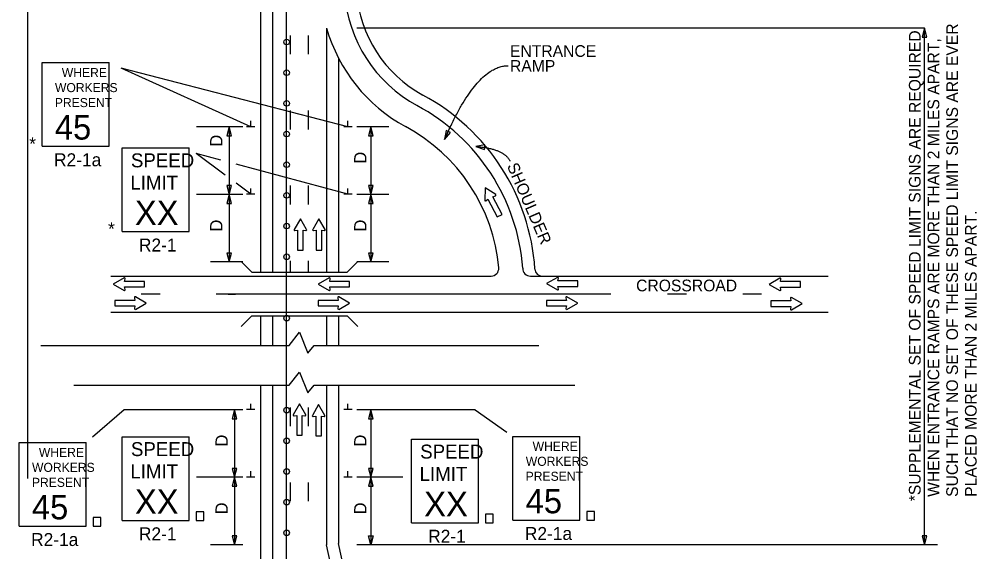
# Model space of a CAD drawing. Extents: x 16115 to 18454, y 4946 to 8326.
# Drawn here: x 16727 to 17413, y 7596 to 7978 of the extents above; entities that cross this region are included whole.
import ezdxf

# ---------------------------------------------------------------- set-up
doc = ezdxf.new("R2010")
doc.units = 0
for name, color, linetype in [('BORDER', 7, 'Continuous'), ('Level 10', 7, 'Continuous'), ('MT_SCRATCH_LEVEL_E', 7, 'Continuous'), ('PAVT_EDGE_EX', 7, 'Continuous'), ('SCRATCH_LEVEL_A', 7, 'Continuous'), ('TYPICAL_TEXT_DIMEN_EX', 7, 'Continuous')]:
    doc.layers.add(name, color=color, linetype=linetype)

# ---------------------------------------------------------------- blocks, each defined once
blk = doc.blocks.new('FTERM')
at = {"layer": 'BORDER'}
for p, q in [((-5.862, 0), (-5.862, 1.571)), ((-5.862, 1.571), (0, 0)), ((0, 0), (-5.862, -1.571)), ((-5.862, -1.571), (-5.862, 0))]:
    blk.add_line(p, q, dxfattribs=at)

msp = doc.modelspace()

# ---------------------------------------------------------------- linework, layer by layer
at = {"layer": 'BORDER'}
for p, q in [((17375.66, 7971.33), (16968.59, 7971.33)), ((17375.66, 7971.33), (17373.96, 7964.93)), ((17375.66, 7600.76), (17375.66, 7971.33)), ((17377.35, 7964.93), (17375.66, 7971.33)), ((17373.96, 7964.93), (17375.66, 7964.93)), ((17375.66, 7964.93), (17377.35, 7964.93)), ((16962.35, 7900.56), (16799.79, 7942.58)), ((16892.63, 7900.56), (16799.79, 7942.58)), ((16892.63, 7900.56), (16892.63, 7904.75)), ((16962.35, 7900.56), (16962.35, 7904.75)), ((16886.89, 7900.47), (16853.73, 7900.47)), ((16877.08, 7900.47), (16875.39, 7894.06)), ((16877.08, 7900.47), (16877.08, 7852.03)), ((16878.78, 7894.06), (16877.08, 7900.47)), ((16895.66, 7900.56), (16889.61, 7900.56)), ((16965.37, 7900.56), (16959.32, 7900.56)), ((16991.66, 7900.47), (16968.59, 7900.47)), ((16978.69, 7900.47), (16977, 7894.06)), ((16978.69, 7900.47), (16978.69, 7852.03)), ((16980.39, 7894.06), (16978.69, 7900.47)), ((17032.65, 7897.88), (17031.59, 7891.34)), ((17034.2, 7897.18), (17032.65, 7897.88)), ((17035.74, 7896.49), (17034.2, 7897.18)), ((16875.39, 7894.06), (16877.08, 7894.06)), ((16877.08, 7894.06), (16878.78, 7894.06)), ((16977, 7894.06), (16978.69, 7894.06)), ((16978.69, 7894.06), (16980.39, 7894.06)), ((17031.59, 7891.34), (17035.74, 7896.49)), ((17060.53, 7887.65), (17054.02, 7886.43)), ((17054.02, 7886.43), (17060.28, 7884.27)), ((17060.28, 7884.27), (17060.41, 7885.96)), ((17060.41, 7885.96), (17060.53, 7887.65)), ((16874.33, 7865.82), (16853.48, 7881.41)), ((16871.29, 7876.62), (16853.48, 7881.41)), ((16962.35, 7852.13), (16882.2, 7873.69)), ((16877.08, 7858.44), (16875.39, 7858.44)), ((16875.39, 7858.44), (16877.08, 7852.03)), ((16877.08, 7852.03), (16878.78, 7858.44)), ((16878.78, 7858.44), (16877.08, 7858.44)), ((16892.63, 7852.13), (16882.06, 7860.04)), ((16892.63, 7852.13), (16892.63, 7856.32)), ((16962.35, 7852.13), (16962.35, 7856.32)), ((16978.69, 7858.44), (16977, 7858.44)), ((16977, 7858.44), (16978.69, 7852.03)), ((16978.69, 7852.03), (16980.39, 7858.44)), ((16980.39, 7858.44), (16978.69, 7858.44)), ((16886.89, 7852.03), (16853.73, 7852.03)), ((16877.08, 7852.03), (16875.39, 7845.63)), ((16877.08, 7852.03), (16877.08, 7803.6)), ((16878.78, 7845.63), (16877.08, 7852.03)), ((16895.66, 7852.13), (16889.61, 7852.13)), ((16965.37, 7852.13), (16959.32, 7852.13)), ((16991.66, 7852.03), (16968.59, 7852.03)), ((16978.69, 7852.03), (16977, 7845.63)), ((16978.69, 7852.03), (16978.69, 7803.6)), ((16980.39, 7845.63), (16978.69, 7852.03)), ((16875.39, 7845.63), (16877.08, 7845.63)), ((16877.08, 7845.63), (16878.78, 7845.63)), ((16977, 7845.63), (16978.69, 7845.63)), ((16978.69, 7845.63), (16980.39, 7845.63)), ((16877.08, 7810.01), (16875.39, 7810.01)), ((16875.39, 7810.01), (16877.08, 7803.6)), ((16877.08, 7803.6), (16878.78, 7810.01)), ((16878.78, 7810.01), (16877.08, 7810.01)), ((16978.69, 7810.01), (16977, 7810.01)), ((16977, 7810.01), (16978.69, 7803.6)), ((16978.69, 7803.6), (16980.39, 7810.01)), ((16980.39, 7810.01), (16978.69, 7810.01)), ((16886.89, 7803.6), (16863.83, 7803.6)), ((16991.66, 7803.6), (16968.59, 7803.6)), ((16742.11, 7743.77), (16920.18, 7743.77)), ((16938.04, 7743.77), (17099.27, 7743.77)), ((16765.79, 7715.22), (16920.18, 7715.22)), ((16938.04, 7715.22), (17124.97, 7715.22)), ((16801.89, 7697.62), (16779.08, 7678.07)), ((16886.89, 7697.62), (16801.89, 7697.62)), ((16880.94, 7697.62), (16879.24, 7691.22)), ((16880.94, 7697.62), (16880.94, 7649.19)), ((16882.63, 7691.22), (16880.94, 7697.62)), ((16895.66, 7697.72), (16889.61, 7697.72)), ((16892.63, 7697.72), (16892.63, 7701.91)), ((16965.37, 7697.72), (16959.32, 7697.72)), ((16962.35, 7697.72), (16962.35, 7701.91)), ((17053.59, 7697.62), (16968.59, 7697.62)), ((16978.69, 7697.62), (16977, 7691.22)), ((16978.69, 7697.62), (16978.69, 7649.19)), ((16980.39, 7691.22), (16978.69, 7697.62)), ((17053.59, 7697.62), (17076.23, 7681.62)), ((16879.24, 7691.22), (16880.94, 7691.22)), ((16880.94, 7691.22), (16882.63, 7691.22)), ((16977, 7691.22), (16978.69, 7691.22)), ((16978.69, 7691.22), (16980.39, 7691.22)), ((16880.94, 7655.6), (16879.24, 7655.6)), ((16879.24, 7655.6), (16880.94, 7649.19)), ((16880.94, 7649.19), (16882.63, 7655.6)), ((16882.63, 7655.6), (16880.94, 7655.6)), ((16892.63, 7649.29), (16892.63, 7653.48)), ((16962.35, 7649.29), (16962.35, 7653.48)), ((16978.69, 7655.6), (16977, 7655.6)), ((16977, 7655.6), (16978.69, 7649.19)), ((16978.69, 7649.19), (16980.39, 7655.6)), ((16980.39, 7655.6), (16978.69, 7655.6)), ((16886.89, 7649.19), (16853.73, 7649.19)), ((16880.94, 7649.19), (16879.24, 7642.79)), ((16879.24, 7642.79), (16880.94, 7642.79)), ((16880.94, 7649.19), (16880.94, 7600.76)), ((16882.63, 7642.79), (16880.94, 7649.19)), ((16880.94, 7642.79), (16882.63, 7642.79)), ((16895.66, 7649.29), (16889.61, 7649.29)), ((16965.37, 7649.29), (16959.32, 7649.29)), ((17001.75, 7649.19), (16968.59, 7649.19)), ((16978.69, 7649.19), (16977, 7642.79)), ((16977, 7642.79), (16978.69, 7642.79)), ((16978.69, 7649.19), (16978.69, 7600.76)), ((16980.39, 7642.79), (16978.69, 7649.19)), ((16978.69, 7642.79), (16980.39, 7642.79)), ((16880.94, 7607.17), (16879.24, 7607.17)), ((16879.24, 7607.17), (16880.94, 7600.76)), ((16880.94, 7600.76), (16882.63, 7607.17)), ((16882.63, 7607.17), (16880.94, 7607.17)), ((17375.66, 7607.17), (17373.96, 7607.17)), ((17373.96, 7607.17), (17375.66, 7600.76)), ((17375.66, 7600.76), (17377.35, 7607.17)), ((17377.35, 7607.17), (17375.66, 7607.17)), ((16886.89, 7600.76), (16863.83, 7600.76)), ((17384.95, 7600.76), (16968.59, 7600.76))]:
    msp.add_line(p, q, dxfattribs=at)
msp.add_lwpolyline([(16918.32, 7255.33), (16918.32, 8189.12)], dxfattribs=at)
for centre in [(16918.32, 7961.33), (16918.32, 7939.33), (16918.32, 7917.33), (16918.32, 7895.33), (16918.32, 7873.33), (16918.32, 7851.33), (16918.32, 7829.33), (16918.32, 7807.33), (16918.32, 7763.33), (16918.32, 7697.33), (16918.32, 7675.33), (16918.32, 7653.33), (16918.32, 7631.33), (16918.32, 7609.33)]:
    msp.add_circle(centre, 2, dxfattribs=at)
for points in [[(17031.62, 7891.38), (17054.35, 7944.33), (17077.07, 7944.33)], [(17054.02, 7886.43), (17074.27, 7884.94), (17078.5, 7875.93)]]:
    msp.add_open_spline(points, degree=2, dxfattribs=at)
at = {"layer": 'Level 10'}
for p, q in [((16743.01, 7946.55), (16791.01, 7946.55)), ((16743.01, 7886.55), (16743.01, 7946.55)), ((16791.01, 7886.55), (16791.01, 7946.55)), ((16743.01, 7886.55), (16791.01, 7886.55)), ((16800.44, 7885.4), (16848.44, 7885.4)), ((16800.44, 7825.4), (16800.44, 7885.4)), ((16848.44, 7825.4), (16848.44, 7885.4)), ((16800.44, 7825.4), (16848.44, 7825.4)), ((16800.44, 7678.3), (16848.44, 7678.3)), ((16800.44, 7618.3), (16800.44, 7678.3)), ((16848.44, 7618.3), (16848.44, 7678.3)), ((17080.59, 7678.54), (17128.59, 7678.54)), ((17080.59, 7618.54), (17080.59, 7678.54)), ((17128.59, 7618.54), (17128.59, 7678.54)), ((16726.57, 7674.21), (16774.57, 7674.21)), ((16726.57, 7614.21), (16726.57, 7674.21)), ((16774.57, 7614.21), (16774.57, 7674.21)), ((17007.83, 7676.54), (17055.83, 7676.54)), ((17007.83, 7616.54), (17007.83, 7676.54)), ((17055.83, 7616.54), (17055.83, 7676.54)), ((16800.44, 7618.3), (16848.44, 7618.3)), ((17007.83, 7616.54), (17055.83, 7616.54)), ((17080.59, 7618.54), (17128.59, 7618.54)), ((16726.57, 7614.21), (16774.57, 7614.21))]:
    msp.add_line(p, q, dxfattribs=at)
for points in [[(16853.46, 7618.3), (16859.05, 7618.3), (16859.05, 7624.47), (16853.46, 7624.47)], [(17060.85, 7616.54), (17066.44, 7616.54), (17066.44, 7622.71), (17060.85, 7622.71)], [(17133.6, 7618.54), (17139.2, 7618.54), (17139.2, 7624.71), (17133.6, 7624.71)], [(16779.59, 7614.21), (16785.18, 7614.21), (16785.18, 7620.38), (16779.59, 7620.38)]]:
    msp.add_lwpolyline(points, close=True, dxfattribs=at)
at = {"layer": 'MT_SCRATCH_LEVEL_E'}
for p, q in [((17060.69, 7856.76), (17060.35, 7847.8)), ((17068.24, 7851.9), (17060.69, 7856.76)), ((17061.15, 7847.39), (17062.69, 7848.57)), ((17062.69, 7848.57), (17069.27, 7835.91)), ((17066.27, 7850.43), (17068.12, 7851.01)), ((17072.84, 7837.76), (17066.27, 7850.43)), ((17069.27, 7835.91), (17072.84, 7837.76)), ((16928.22, 7834.63), (16923.79, 7826.84)), ((16932.68, 7826.84), (16928.22, 7834.63)), ((16941.46, 7834.63), (16937.03, 7826.84)), ((16945.92, 7826.84), (16941.46, 7834.63)), ((16924.31, 7826.1), (16926.22, 7826.44)), ((16926.22, 7826.44), (16926.22, 7812.17)), ((16930.25, 7812.17), (16930.25, 7826.44)), ((16930.25, 7826.44), (16932.16, 7826.1)), ((16937.55, 7826.1), (16939.46, 7826.44)), ((16939.46, 7826.44), (16939.46, 7812.17)), ((16943.49, 7812.17), (16943.49, 7826.44)), ((16943.49, 7826.44), (16945.4, 7826.1)), ((16926.22, 7812.17), (16930.25, 7812.17)), ((16939.46, 7812.17), (16943.49, 7812.17)), ((16801.82, 7792.13), (16794.02, 7787.67)), ((16801.82, 7792.13), (16794.02, 7787.67)), ((16794.02, 7787.67), (16801.82, 7783.24)), ((16794.02, 7787.67), (16801.82, 7783.24)), ((16802.21, 7789.7), (16802.55, 7791.62)), ((16802.21, 7789.7), (16802.55, 7791.62)), ((16816.48, 7789.7), (16802.21, 7789.7)), ((16816.48, 7789.7), (16802.21, 7789.7)), ((16816.48, 7785.68), (16816.48, 7789.7)), ((16816.48, 7785.68), (16816.48, 7789.7)), ((16948.83, 7792.13), (16941.04, 7787.67)), ((16948.83, 7792.13), (16941.04, 7787.67)), ((16941.04, 7787.67), (16948.83, 7783.24)), ((16941.04, 7787.67), (16948.83, 7783.24)), ((16949.23, 7789.7), (16949.57, 7791.62)), ((16949.23, 7789.7), (16949.57, 7791.62)), ((16963.5, 7789.7), (16949.23, 7789.7)), ((16963.5, 7789.7), (16949.23, 7789.7)), ((16963.5, 7785.68), (16963.5, 7789.7)), ((16963.5, 7785.68), (16963.5, 7789.7)), ((17112.45, 7792.54), (17104.66, 7788.07)), ((17112.45, 7792.54), (17104.66, 7788.07)), ((17104.66, 7788.07), (17112.45, 7783.65)), ((17104.66, 7788.07), (17112.45, 7783.65)), ((17112.85, 7790.11), (17113.19, 7792.02)), ((17112.85, 7790.11), (17113.19, 7792.02)), ((17127.12, 7790.11), (17112.85, 7790.11)), ((17127.12, 7790.11), (17112.85, 7790.11)), ((17127.12, 7786.08), (17127.12, 7790.11)), ((17127.12, 7786.08), (17127.12, 7790.11)), ((17272.01, 7791.93), (17264.22, 7787.47)), ((17272.01, 7791.93), (17264.22, 7787.47)), ((17264.22, 7787.47), (17272.01, 7783.05)), ((17264.22, 7787.47), (17272.01, 7783.05)), ((17272.41, 7789.51), (17272.74, 7791.42)), ((17272.41, 7789.51), (17272.74, 7791.42)), ((17286.67, 7789.51), (17272.41, 7789.51)), ((17286.67, 7789.51), (17272.41, 7789.51)), ((17286.67, 7785.48), (17286.67, 7789.51)), ((17286.67, 7785.48), (17286.67, 7789.51)), ((16802.55, 7783.76), (16802.21, 7785.68)), ((16802.21, 7785.68), (16816.48, 7785.68)), ((16802.55, 7783.76), (16802.21, 7785.68)), ((16802.21, 7785.68), (16816.48, 7785.68)), ((16949.57, 7783.76), (16949.23, 7785.68)), ((16949.23, 7785.68), (16963.5, 7785.68)), ((16949.57, 7783.76), (16949.23, 7785.68)), ((16949.23, 7785.68), (16963.5, 7785.68)), ((17113.19, 7784.17), (17112.85, 7786.08)), ((17112.85, 7786.08), (17127.12, 7786.08)), ((17113.19, 7784.17), (17112.85, 7786.08)), ((17112.85, 7786.08), (17127.12, 7786.08)), ((17272.74, 7783.57), (17272.41, 7785.48)), ((17272.41, 7785.48), (17286.67, 7785.48)), ((17272.74, 7783.57), (17272.41, 7785.48)), ((17272.41, 7785.48), (17286.67, 7785.48)), ((16809.52, 7776.08), (16795.25, 7776.08)), ((16795.25, 7776.08), (16795.25, 7772.06)), ((16809.52, 7776.08), (16795.25, 7776.08)), ((16795.25, 7776.08), (16795.25, 7772.06)), ((16809.18, 7778), (16809.52, 7776.08)), ((16809.18, 7778), (16809.52, 7776.08)), ((16817.71, 7774.09), (16809.92, 7778.51)), ((16817.71, 7774.09), (16809.92, 7778.51)), ((16809.92, 7769.63), (16817.71, 7774.09)), ((16809.92, 7769.63), (16817.71, 7774.09)), ((16955.32, 7776.08), (16941.05, 7776.08)), ((16941.05, 7776.08), (16941.05, 7772.06)), ((16955.32, 7776.08), (16941.05, 7776.08)), ((16941.05, 7776.08), (16941.05, 7772.06)), ((16954.98, 7778), (16955.32, 7776.08)), ((16954.98, 7778), (16955.32, 7776.08)), ((16963.51, 7774.09), (16955.72, 7778.51)), ((16963.51, 7774.09), (16955.72, 7778.51)), ((16955.72, 7769.63), (16963.51, 7774.09)), ((16955.72, 7769.63), (16963.51, 7774.09)), ((17118.94, 7776.08), (17104.67, 7776.08)), ((17104.67, 7776.08), (17104.67, 7772.06)), ((17118.94, 7776.08), (17104.67, 7776.08)), ((17104.67, 7776.08), (17104.67, 7772.06)), ((17118.6, 7778), (17118.94, 7776.08)), ((17118.6, 7778), (17118.94, 7776.08)), ((17127.13, 7774.09), (17119.34, 7778.51)), ((17127.13, 7774.09), (17119.34, 7778.51)), ((17119.34, 7769.63), (17127.13, 7774.09)), ((17119.34, 7769.63), (17127.13, 7774.09)), ((17279.9, 7775.78), (17265.63, 7775.78)), ((17265.63, 7775.78), (17265.63, 7771.75)), ((17279.9, 7775.78), (17265.63, 7775.78)), ((17265.63, 7775.78), (17265.63, 7771.75)), ((17279.56, 7777.69), (17279.9, 7775.78)), ((17279.56, 7777.69), (17279.9, 7775.78)), ((17288.09, 7773.78), (17280.3, 7778.21)), ((17288.09, 7773.78), (17280.3, 7778.21)), ((17280.3, 7769.32), (17288.09, 7773.78)), ((17280.3, 7769.32), (17288.09, 7773.78)), ((16795.25, 7772.06), (16809.52, 7772.06)), ((16795.25, 7772.06), (16809.52, 7772.06)), ((16809.52, 7772.06), (16809.18, 7770.14)), ((16809.52, 7772.06), (16809.18, 7770.14)), ((16941.05, 7772.06), (16955.32, 7772.06)), ((16941.05, 7772.06), (16955.32, 7772.06)), ((16955.32, 7772.06), (16954.98, 7770.14)), ((16955.32, 7772.06), (16954.98, 7770.14)), ((17104.67, 7772.06), (17118.94, 7772.06)), ((17104.67, 7772.06), (17118.94, 7772.06)), ((17118.94, 7772.06), (17118.6, 7770.14)), ((17118.94, 7772.06), (17118.6, 7770.14)), ((17265.63, 7771.75), (17279.9, 7771.75)), ((17265.63, 7771.75), (17279.9, 7771.75)), ((17279.9, 7771.75), (17279.56, 7769.84)), ((17279.9, 7771.75), (17279.56, 7769.84)), ((16927.57, 7701.78), (16923.14, 7693.99)), ((16932.03, 7693.99), (16927.57, 7701.78)), ((16941.22, 7701.32), (16936.79, 7693.53)), ((16945.68, 7693.53), (16941.22, 7701.32)), ((16923.66, 7693.25), (16925.58, 7693.59)), ((16925.58, 7693.59), (16925.58, 7679.32)), ((16929.6, 7679.32), (16929.6, 7693.59)), ((16929.6, 7693.59), (16931.52, 7693.25)), ((16937.31, 7692.79), (16939.22, 7693.13)), ((16939.22, 7693.13), (16939.22, 7678.86)), ((16943.25, 7678.86), (16943.25, 7693.13)), ((16943.25, 7693.13), (16945.16, 7692.79)), ((16925.58, 7679.32), (16929.6, 7679.32)), ((16939.22, 7678.86), (16943.25, 7678.86))]:
    msp.add_line(p, q, dxfattribs=at)
for centre, start, end in [((17067.96, 7851.48), 287.48456, 57.22148), ((17060.85, 7847.79), 177.8732, 307.41217), ((16924.23, 7826.6), 150.42484, 279.96381), ((16932.24, 7826.6), 260.03619, 29.77312), ((16937.47, 7826.6), 150.42484, 279.96381), ((16945.48, 7826.6), 260.03619, 29.77312), ((16802.06, 7791.69), 350.03619, 119.77312), ((16802.06, 7791.69), 350.03619, 119.77312), ((16949.07, 7791.69), 350.03619, 119.77312), ((16949.07, 7791.69), 350.03619, 119.77312), ((17112.69, 7792.1), 350.03619, 119.77312), ((17112.69, 7792.1), 350.03619, 119.77312), ((17272.25, 7791.49), 350.03619, 119.77312), ((17272.25, 7791.49), 350.03619, 119.77312), ((16802.06, 7783.68), 240.42484, 9.96381), ((16802.06, 7783.68), 240.42484, 9.96381), ((16949.08, 7783.68), 240.42484, 9.96381), ((16949.08, 7783.68), 240.42484, 9.96381), ((17112.7, 7784.09), 240.42484, 9.96381), ((17112.7, 7784.09), 240.42484, 9.96381), ((17272.25, 7783.49), 240.42484, 9.96381), ((17272.25, 7783.49), 240.42484, 9.96381), ((16809.68, 7778.08), 60.42484, 189.96381), ((16809.68, 7778.08), 60.42484, 189.96381), ((16955.48, 7778.08), 60.42484, 189.96381), ((16955.48, 7778.08), 60.42484, 189.96381), ((17119.1, 7778.08), 60.42484, 189.96381), ((17119.1, 7778.08), 60.42484, 189.96381), ((17280.05, 7777.77), 60.42484, 189.96381), ((17280.05, 7777.77), 60.42484, 189.96381), ((16809.68, 7770.07), 170.03619, 299.77312), ((16809.68, 7770.07), 170.03619, 299.77312), ((16955.48, 7770.07), 170.03619, 299.77312), ((16955.48, 7770.07), 170.03619, 299.77312), ((17119.1, 7770.07), 170.03619, 299.77312), ((17119.1, 7770.07), 170.03619, 299.77312), ((17280.06, 7769.76), 170.03619, 299.77312), ((17280.06, 7769.76), 170.03619, 299.77312), ((16923.58, 7693.74), 150.42484, 279.96381), ((16931.59, 7693.74), 260.03619, 29.77312), ((16937.23, 7693.29), 150.42484, 279.96381), ((16945.24, 7693.29), 260.03619, 29.77312)]:
    msp.add_arc(centre, 0.498, start, end, dxfattribs=at)
at = {"layer": 'PAVT_EDGE_EX'}
for p, q in [((16899.59, 8189.12), (16899.59, 7796.21)), ((16908.2, 8189.12), (16908.2, 7796.21)), ((16946.95, 7971.33), (16946.95, 7796.21)), ((16955.56, 7949.75), (16955.56, 7796.21)), ((16885.79, 7803.82), (16893.4, 7796.21)), ((16969.36, 7803.82), (16961.75, 7796.21)), ((16792.22, 7793.52), (17065.04, 7793.52)), ((16893.4, 7796.21), (16961.75, 7796.21)), ((17093.11, 7793.52), (17306.6, 7793.52)), ((16792.22, 7767.69), (17306.6, 7767.69)), ((16893.4, 7765), (16885.79, 7757.39)), ((16893.4, 7765), (16961.75, 7765)), ((16899.59, 7765), (16899.59, 7743.77)), ((16908.2, 7765), (16908.2, 7743.77)), ((16946.95, 7765), (16946.95, 7743.77)), ((16955.56, 7765), (16955.56, 7743.77)), ((16961.75, 7765), (16969.36, 7757.39)), ((16899.59, 7715.22), (16899.59, 7314.27)), ((16908.2, 7715.22), (16908.2, 7314.27)), ((16946.95, 7715.22), (16946.95, 7600.76)), ((16955.51, 7715.22), (16955.51, 7601.63)), ((16968.39, 7542.71), (16955.51, 7601.63)), ((16959.83, 7541.84), (16946.95, 7600.76))]:
    msp.add_line(p, q, dxfattribs=at)
for centre, radius, start, end in [((17060.03, 8003.94), 100.47, 184.18699, 241.32804), ((17060.03, 8003.94), 91.87, 184.18699, 241.32804), ((17060.03, 8003.94), 117.69, 196.08461, 241.32804), ((16943.45, 7788.31), 153.26, 3.82656, 61.76587), ((16943.45, 7788.31), 144.65, 4.28948, 61.79192), ((16943.45, 7788.31), 127.43, 4.97638, 61.85461), ((17065.04, 7798.9), 5.38, 270, 4.97638), ((17093.11, 7798.9), 5.4, 177.54481, 270), ((17101.74, 7798.9), 5.38, 183.82656, 270)]:
    msp.add_arc(centre, radius, start, end, dxfattribs=at)
at = {"layer": 'SCRATCH_LEVEL_A'}
for p, q in [((16732.78, 7648.38), (16732.78, 8300.7)), ((17150.78, 7780.61), (16876.54, 7780.61))]:
    msp.add_line(p, q, dxfattribs=at)
for points in [[(16921.12, 7952.52), (16921.12, 7965.97)], [(16934.03, 7952.52), (16934.03, 7965.97)], [(16921.12, 7898.71), (16921.12, 7912.16)], [(16934.03, 7898.71), (16934.03, 7912.16)], [(16921.12, 7844.89), (16921.12, 7858.35)], [(16934.03, 7844.89), (16934.03, 7858.35)], [(16921.12, 7796.21), (16921.12, 7804.53)], [(16934.03, 7796.21), (16934.03, 7804.53)], [(16827.56, 7780.61), (16814.11, 7780.61)], [(16881.38, 7780.61), (16867.92, 7780.61)], [(16876.54, 7780.61), (16881.72, 7780.61)], [(16935.53, 7780.61), (16922.08, 7780.61)], [(16989.35, 7780.61), (16975.89, 7780.61)], [(17043.16, 7780.61), (17029.71, 7780.61)], [(17096.97, 7780.61), (17083.52, 7780.61)], [(17150.78, 7780.61), (17137.33, 7780.61)], [(17204.99, 7780.61), (17191.53, 7780.61)], [(17258.8, 7780.61), (17245.35, 7780.61)], [(16921.12, 7685.83), (16921.12, 7699.28)], [(16934.03, 7685.83), (16934.03, 7699.28)], [(16921.12, 7632.02), (16921.12, 7645.47)], [(16934.03, 7632.02), (16934.03, 7645.47)]]:
    msp.add_lwpolyline(points, dxfattribs=at)
at = {"layer": 'TYPICAL_TEXT_DIMEN_EX'}
for p, q in [((16933.54, 7738.26), (16938.04, 7743.77)), ((16933.54, 7709.71), (16938.04, 7715.22))]:
    msp.add_line(p, q, dxfattribs=at)
for points in [[(16908.2, 7743.77), (16920.18, 7743.77), (16927.57, 7753.2), (16933.54, 7738.26)], [(16908.2, 7715.22), (16920.18, 7715.22), (16927.57, 7724.65), (16933.54, 7709.71)]]:
    msp.add_lwpolyline(points, dxfattribs=at)

# ---------------------------------------------------------------- block references
at = {"layer": 'BORDER', "xscale": 1.0924066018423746, "yscale": 1.0789902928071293, "rotation": -90}
msp.add_blockref('FTERM', (16978.69, 7600.76), dxfattribs=at)

# ---------------------------------------------------------------- texts
at = {"layer": 'BORDER'}
for s, height, rotation, p in [(' SUCH THAT NO SET OF THESE SPEED LIMIT SIGNS ARE EVER', 8.4, 90, (17399.71, 7632.01)), ('*SUPPLEMENTAL SET OF SPEED LIMIT SIGNS ARE REQUIRED', 8.4, 90, (17372.91, 7632.01)), ('ENTRANCE', 8.4, 360, (17078.52, 7950.68)), (' WHEN ENTRANCE RAMPS ARE MORE THAN 2 MILES APART,', 8.4, 90, (17386.31, 7632.01)), ('RAMP', 8.4, 360, (17078.52, 7940)), ('D', 8.83, 90, (16872.3, 7886.29)), ('D', 8.83, 90, (16975.58, 7874.09)), ('SHOULDER', 8.4, 293.35307, (17076.17, 7872.55)), (' PLACED MORE THAN 2 MILES APART.', 8.4, 90, (17413.11, 7632.01)), ('D', 8.83, 90, (16872.3, 7825.44)), ('D', 8.83, 90, (16975.58, 7825.44)), ('CROSSROAD', 8.4, 360, (17168.93, 7782.53)), ('D', 8.83, 90, (16876.15, 7671.25)), ('D', 8.83, 90, (16975.58, 7671.25)), ('D', 8.83, 90, (16876.15, 7622.6)), ('D', 8.83, 90, (16975.58, 7622.6))]:
    msp.add_text(s, height=height, rotation=rotation, dxfattribs=at).set_placement(p)
for p in [(16733.78, 7883.7), (16790.32, 7822.74)]:
    msp.add_text('*', height=9.3, dxfattribs=at).set_placement(p)
at = {"layer": 'Level 10'}
for s, height, p in [('WHERE', 6.5, (16757.15, 7936.16)), ('WORKERS', 6.5, (16752.24, 7925.41)), ('PRESENT', 6.5, (16752.16, 7914.66)), ('45', 17.538, (16752.15, 7891.37)), ('R2-1a', 9.3, (16751.58, 7872.25)), ('SPEED', 10, (16806.73, 7871.48)), ('LIMIT', 10, (16806.32, 7855.48)), ('XX', 17.538, (16809.57, 7830.1)), ('R2-1', 9.3, (16812.45, 7811.1)), ('WHERE', 6.5, (16740.71, 7663.81)), ('SPEED', 10, (16806.73, 7664.38)), ('SPEED', 10, (17014.12, 7662.62)), ('WHERE', 6.5, (17094.73, 7668.15)), ('WORKERS', 6.5, (17089.82, 7657.4)), ('WORKERS', 6.5, (16735.8, 7653.06)), ('LIMIT', 10, (16806.32, 7648.38)), ('LIMIT', 10, (17013.71, 7646.62)), ('PRESENT', 6.5, (17089.73, 7646.65)), ('PRESENT', 6.5, (16735.72, 7642.31)), ('45', 17.538, (16735.71, 7619.02)), ('XX', 17.538, (16809.57, 7623)), ('XX', 17.538, (17016.96, 7621.24)), ('45', 17.538, (17089.72, 7623.36)), ('R2-1a', 9.3, (16735.14, 7599.91)), ('R2-1', 9.3, (16812.45, 7604)), ('R2-1', 9.3, (17019.84, 7602.24)), ('R2-1a', 9.3, (17089.16, 7604.24))]:
    msp.add_text(s, height=height, dxfattribs=at).set_placement(p)

doc.saveas('drawing.dxf')
